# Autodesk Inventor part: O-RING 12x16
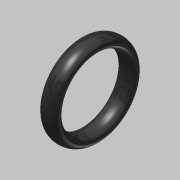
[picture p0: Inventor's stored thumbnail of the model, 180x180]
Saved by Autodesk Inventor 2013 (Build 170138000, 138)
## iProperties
Created: 2020-02
Part Number: O-RING 12x16
Material: 고무
Document SubType Name: Modeling
Designer: mduedu
Density: 1 g/cm^3
Author: mduedu
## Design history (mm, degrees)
sketch "스케치1"
  geometry: L1 (-2.24, 0)-(2.24, 0) reference; L2 (-1.6, 7)-(1.6, 7); L3 (0, 8)-(0, 6); 6 further points; 1 other entity
  constraints: 4 end point, 3 coincident, 2 midpoint, 1 horizontal, 1 vertical, 1 vertical alignment, 6 other
  dimensions: "d0" = 1.6 distance of point (1.6, 7) point (0, 7); "d2" = 12 diameter of point (0, 6) L1; "d3" = 16 diameter of point (0, 8) L1
revolve "회전1" sketch "스케치1" stored, may be unused: angle "d4" = 90 deg
node "솔리드1"
